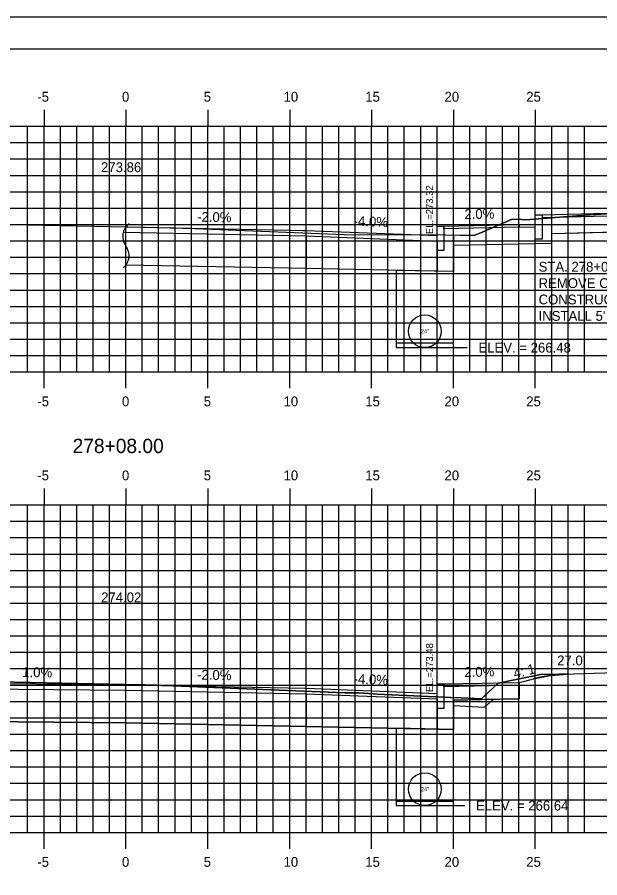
# Model space of a CAD drawing. Extents: x 854453 to 854623, y 366268 to 366378.
# Drawn here: x 854529.8 to 854565.4, y 366325.6 to 366378.2 of the extents above; entities that cross this region are included whole.
import ezdxf

# ---------------------------------------------------------------- set-up
doc = ezdxf.new("R2010")
doc.units = 0
for name, color, linetype in [('ANNOTATION', 7, 'Continuous'), ('BORDER', 7, 'Continuous'), ('D_Curb_Type1_Rt', 7, 'Continuous'), ('D_Curb_Type_1_Rt', 7, 'Continuous'), ('D_Roadway_Centerline', 7, 'Continuous'), ('D_Roadway_Centerline_Text', 7, 'Continuous'), ('D_Roadway_Edge_Shoulder', 7, 'Continuous'), ('D_Roadway_FinishedGrade', 7, 'Continuous'), ('D_Roadway_Sidewalks_Paved', 7, 'Continuous'), ('D_Roadway_SubGrade', 7, 'Continuous'), ('D_Text_Standard', 7, 'Continuous'), ('H_V ANNOTATION', 7, 'Continuous'), ('JUNK COM EXC', 7, 'Continuous'), ('junk grubnfill', 7, 'Continuous'), ('junk strct exc', 7, 'Continuous'), ('MAJOR', 7, 'Continuous'), ('MINOR', 7, 'Continuous'), ('PDRAIN', 7, 'Continuous'), ('PLOT BOUNDARY', 7, 'Continuous'), ('S_Roadway_Centerline', 7, 'Continuous')]:
    doc.layers.add(name, color=color, linetype=linetype)

msp = doc.modelspace()

# ---------------------------------------------------------------- linework, layer by layer
at = {"layer": 'BORDER'}
msp.add_line((854621.439, 366376.236), (854461.439, 366376.236), dxfattribs=at)
at = {"layer": 'D_Curb_Type1_Rt'}
msp.add_lwpolyline([(854561.855, 366366.118), (854561.855, 366364.618), (854561.439, 366364.618), (854561.439, 366366.118)], close=True, dxfattribs=at)
at = {"layer": 'D_Curb_Type_1_Rt'}
for points in [[(854555.855, 366365.423), (854555.855, 366363.923), (854555.439, 366363.923), (854555.439, 366365.423)], [(854555.855, 366337.466), (854555.855, 366335.966), (854555.439, 366335.966), (854555.439, 366337.466)]]:
    msp.add_lwpolyline(points, close=True, dxfattribs=at)
at = {"layer": 'D_Roadway_Centerline'}
msp.add_line((854547.246, 366365.163), (854547.439, 366365.159), dxfattribs=at)
at = {"layer": 'D_Roadway_Edge_Shoulder'}
for p, q in [((854536.439, 366365.379), (854547.439, 366365.159)), ((854547.439, 366365.159), (854555.437, 366364.84))]:
    msp.add_line(p, q, dxfattribs=at)
msp.add_lwpolyline([(854517.439, 366337.212), (854525.439, 366337.532), (854536.439, 366337.422), (854547.439, 366337.202), (854555.437, 366336.882)], dxfattribs=at)
at = {"layer": 'D_Roadway_FinishedGrade'}
msp.add_line((854560.444, 366337.557), (854561.318, 366337.776), dxfattribs=at)
msp.add_arc((854563.744, 366328.074), 10, 91.7748, 104.0362, dxfattribs=at)
at = {"layer": 'D_Roadway_Sidewalks_Paved'}
for p, q in [((854561.855, 366366.118), (854574.919, 366366.457)), ((854561.855, 366365.951), (854574.919, 366366.291)), ((854560.444, 366365.515), (854561.439, 366365.534)), ((854560.447, 366365.348), (854561.442, 366365.368))]:
    msp.add_line(p, q, dxfattribs=at)
for points in [[(854555.855, 366365.423), (854560.444, 366365.515), (854560.444, 366365.348), (854555.855, 366365.256)], [(854555.855, 366337.465), (854560.444, 366337.557), (854560.444, 366337.39), (854555.855, 366337.298)]]:
    msp.add_lwpolyline(points, close=True, dxfattribs=at)
at = {"layer": 'D_Roadway_SubGrade'}
for p, q in [((854536.278, 366365.049), (854547.439, 366364.826)), ((854562.439, 366364.966), (854574.919, 366365.29)), ((854562.439, 366364.387), (854562.439, 366364.966)), ((854547.439, 366364.826), (854547.439, 366362.826)), ((854556.439, 366364.267), (854562.439, 366364.387)), ((854547.439, 366362.826), (854536.439, 366363.046))]:
    msp.add_line(p, q, dxfattribs=at)
for points in [[(854547.439, 366364.826), (854555.439, 366364.506), (854555.439, 366362.666), (854547.439, 366362.826)], [(854525.439, 366335.199), (854525.439, 366337.199), (854536.439, 366337.089), (854547.439, 366336.869), (854547.439, 366334.869), (854536.439, 366335.089)], [(854547.439, 366336.869), (854555.439, 366336.549), (854555.439, 366334.709), (854547.439, 366334.869)]]:
    msp.add_lwpolyline(points, close=True, dxfattribs=at)
for points in [[(854556.439, 366364.267), (854556.439, 366362.645), (854555.439, 366362.665)], [(854560.444, 366337.39), (854560.444, 366336.557), (854556.439, 366336.477), (854556.439, 366334.688), (854555.439, 366334.708)], [(854556.439, 366336.151), (854558.328, 366336.052), (854558.863, 366336.526)]]:
    msp.add_lwpolyline(points, dxfattribs=at)
for centre, radius, start, end in [((854537.213, 366364.795), 0.969, 126.9306, 216.9306), ((854535.7, 366363.616), 0.933, 307.6674, 38.9085)]:
    msp.add_arc(centre, radius, start, end, dxfattribs=at)
at = {"layer": 'D_Text_Standard'}
for points in [[(854556.439, 366358.001), (854556.606, 366358.001), (854557.286, 366358.001)], [(854556.439, 366330.041), (854556.458, 366330.041), (854557.138, 366330.041)]]:
    msp.add_lwpolyline(points, dxfattribs=at)
at = {"layer": 'JUNK COM EXC'}
for points in [[(854556.439, 366364.877), (854556.439, 366364.267), (854556.439, 366364.267), (854562.439, 366364.387), (854562.439, 366364.966), (854574.919, 366365.29), (854574.919, 366366.457), (854571.334, 366366.391), (854568.525, 366366.364), (854564.488, 366366.083), (854560.855, 366365.814), (854560.601, 366365.825), (854560.033, 366365.848), (854558.145, 366365.029), (854557.7, 366364.856), (854556.439, 366364.877)], [(854525.439, 366335.199), (854536.439, 366335.089), (854547.439, 366334.869), (854556.439, 366334.688), (854556.439, 366336.477), (854558.151, 366336.511), (854560.444, 366336.557), (854560.444, 366337.557), (854560.881, 366337.667), (854561.318, 366337.776), (854562.368, 366337.979), (854563.434, 366338.07), (854562.879, 366338.055), (854562.453, 366338.047), (854561.76, 366338.034), (854561.162, 366337.931), (854560.167, 366337.722), (854559.173, 366337.513), (854558.15, 366336.562), (854556.914, 366336.627), (854556.266, 366336.648), (854551.776, 366336.835), (854551.532, 366336.856), (854550.966, 366336.912), (854550.652, 366336.917), (854549.806, 366336.922), (854538.309, 366337.385), (854537.601, 366337.414), (854537.42, 366337.418), (854526.661, 366337.64)]]:
    msp.add_lwpolyline(points, dxfattribs=at)
at = {"layer": 'junk grubnfill'}
msp.add_lwpolyline([(854558.863, 366336.526), (854556.439, 366336.477), (854556.439, 366336.151), (854558.328, 366336.052), (854558.863, 366336.526)], dxfattribs=at)
at = {"layer": 'junk strct exc'}
for points in [[(854552.939, 366362.716), (854552.939, 366358.301), (854556.439, 366358.301), (854556.439, 366362.645)], [(854552.939, 366334.759), (854552.939, 366330.301), (854556.439, 366330.301), (854556.439, 366334.688)]]:
    msp.add_lwpolyline(points, close=True, dxfattribs=at)
at = {"layer": 'MAJOR'}
for p, q in [((854531.439, 366372.523), (854531.439, 366371.521)), ((854536.439, 366372.523), (854536.439, 366371.521)), ((854541.439, 366372.523), (854541.439, 366371.521)), ((854546.439, 366372.523), (854546.439, 366371.521)), ((854551.439, 366372.523), (854551.439, 366371.521)), ((854556.439, 366372.523), (854556.439, 366371.521)), ((854561.439, 366372.523), (854561.439, 366371.521)), ((854466.439, 366371.521), (854606.439, 366371.521)), ((854531.439, 366356.521), (854531.439, 366371.521)), ((854536.439, 366356.521), (854536.439, 366371.521)), ((854541.439, 366356.521), (854541.439, 366371.521)), ((854546.439, 366356.521), (854546.439, 366371.521)), ((854551.439, 366356.521), (854551.439, 366371.521)), ((854556.439, 366356.521), (854556.439, 366371.521)), ((854561.439, 366356.521), (854561.439, 366371.521)), ((854466.439, 366366.521), (854606.439, 366366.521)), ((854466.439, 366361.521), (854606.439, 366361.521)), ((854466.439, 366356.521), (854606.439, 366356.521)), ((854466.439, 366356.521), (854606.439, 366356.521)), ((854531.439, 366355.519), (854531.439, 366356.521)), ((854536.439, 366355.519), (854536.439, 366356.521)), ((854541.439, 366355.519), (854541.439, 366356.521)), ((854546.439, 366355.519), (854546.439, 366356.521)), ((854551.439, 366355.519), (854551.439, 366356.521)), ((854556.439, 366355.519), (854556.439, 366356.521)), ((854561.439, 366355.519), (854561.439, 366356.521)), ((854531.439, 366349.403), (854531.439, 366348.401)), ((854536.439, 366349.403), (854536.439, 366348.401)), ((854541.439, 366349.403), (854541.439, 366348.401)), ((854546.439, 366349.403), (854546.439, 366348.401)), ((854551.439, 366349.403), (854551.439, 366348.401)), ((854556.439, 366349.403), (854556.439, 366348.401)), ((854561.439, 366349.403), (854561.439, 366348.401)), ((854466.439, 366348.401), (854606.439, 366348.401)), ((854466.439, 366348.401), (854606.439, 366348.401)), ((854531.439, 366328.401), (854531.439, 366348.401)), ((854536.439, 366328.401), (854536.439, 366348.401)), ((854541.439, 366328.401), (854541.439, 366348.401)), ((854546.439, 366328.401), (854546.439, 366348.401)), ((854551.439, 366328.401), (854551.439, 366348.401)), ((854556.439, 366328.401), (854556.439, 366348.401)), ((854561.439, 366328.401), (854561.439, 366348.401)), ((854466.439, 366343.401), (854606.439, 366343.401)), ((854466.439, 366338.401), (854606.439, 366338.401)), ((854466.439, 366333.401), (854606.439, 366333.401)), ((854466.439, 366328.401), (854606.439, 366328.401)), ((854466.439, 366328.401), (854606.439, 366328.401)), ((854531.439, 366327.399), (854531.439, 366328.401)), ((854536.439, 366327.399), (854536.439, 366328.401)), ((854541.439, 366327.399), (854541.439, 366328.401)), ((854546.439, 366327.399), (854546.439, 366328.401)), ((854551.439, 366327.399), (854551.439, 366328.401)), ((854556.439, 366327.399), (854556.439, 366328.401)), ((854561.439, 366327.399), (854561.439, 366328.401))]:
    msp.add_line(p, q, dxfattribs=at)
at = {"layer": 'MINOR'}
for p, q in [((854530.439, 366356.521), (854530.439, 366371.521)), ((854532.439, 366356.521), (854532.439, 366371.521)), ((854533.439, 366356.521), (854533.439, 366371.521)), ((854534.439, 366356.521), (854534.439, 366371.521)), ((854535.439, 366356.521), (854535.439, 366371.521)), ((854537.439, 366356.521), (854537.439, 366371.521)), ((854538.439, 366356.521), (854538.439, 366371.521)), ((854539.439, 366356.521), (854539.439, 366371.521)), ((854540.439, 366356.521), (854540.439, 366371.521)), ((854542.439, 366356.521), (854542.439, 366371.521)), ((854543.439, 366356.521), (854543.439, 366371.521)), ((854544.439, 366356.521), (854544.439, 366371.521)), ((854545.439, 366356.521), (854545.439, 366371.521)), ((854547.439, 366356.521), (854547.439, 366371.521)), ((854548.439, 366356.521), (854548.439, 366371.521)), ((854549.439, 366356.521), (854549.439, 366371.521)), ((854550.439, 366356.521), (854550.439, 366371.521)), ((854552.439, 366356.521), (854552.439, 366371.521)), ((854553.439, 366356.521), (854553.439, 366371.521)), ((854554.439, 366356.521), (854554.439, 366371.521)), ((854555.439, 366356.521), (854555.439, 366371.521)), ((854557.439, 366356.521), (854557.439, 366371.521)), ((854558.439, 366356.521), (854558.439, 366371.521)), ((854559.439, 366356.521), (854559.439, 366371.521)), ((854560.439, 366356.521), (854560.439, 366371.521)), ((854562.439, 366356.521), (854562.439, 366371.521)), ((854563.439, 366356.521), (854563.439, 366371.521)), ((854564.439, 366356.521), (854564.439, 366371.521)), ((854466.439, 366370.521), (854606.439, 366370.521)), ((854466.439, 366369.521), (854606.439, 366369.521)), ((854466.439, 366368.521), (854606.439, 366368.521)), ((854466.439, 366367.521), (854606.439, 366367.521)), ((854466.439, 366365.521), (854606.439, 366365.521)), ((854466.439, 366364.521), (854606.439, 366364.521)), ((854466.439, 366363.521), (854606.439, 366363.521)), ((854466.439, 366362.521), (854606.439, 366362.521)), ((854466.439, 366360.521), (854606.439, 366360.521)), ((854466.439, 366359.521), (854606.439, 366359.521)), ((854466.439, 366358.521), (854606.439, 366358.521)), ((854466.439, 366357.521), (854606.439, 366357.521)), ((854530.439, 366328.401), (854530.439, 366348.401)), ((854532.439, 366328.401), (854532.439, 366348.401)), ((854533.439, 366328.401), (854533.439, 366348.401)), ((854534.439, 366328.401), (854534.439, 366348.401)), ((854535.439, 366328.401), (854535.439, 366348.401)), ((854537.439, 366328.401), (854537.439, 366348.401)), ((854538.439, 366328.401), (854538.439, 366348.401)), ((854539.439, 366328.401), (854539.439, 366348.401)), ((854540.439, 366328.401), (854540.439, 366348.401)), ((854542.439, 366328.401), (854542.439, 366348.401)), ((854543.439, 366328.401), (854543.439, 366348.401)), ((854544.439, 366328.401), (854544.439, 366348.401)), ((854545.439, 366328.401), (854545.439, 366348.401)), ((854547.439, 366328.401), (854547.439, 366348.401)), ((854548.439, 366328.401), (854548.439, 366348.401)), ((854549.439, 366328.401), (854549.439, 366348.401)), ((854550.439, 366328.401), (854550.439, 366348.401)), ((854552.439, 366328.401), (854552.439, 366348.401)), ((854553.439, 366328.401), (854553.439, 366348.401)), ((854554.439, 366328.401), (854554.439, 366348.401)), ((854555.439, 366328.401), (854555.439, 366348.401)), ((854557.439, 366328.401), (854557.439, 366348.401)), ((854558.439, 366328.401), (854558.439, 366348.401)), ((854559.439, 366328.401), (854559.439, 366348.401)), ((854560.439, 366328.401), (854560.439, 366348.401)), ((854562.439, 366328.401), (854562.439, 366348.401)), ((854563.439, 366328.401), (854563.439, 366348.401)), ((854564.439, 366328.401), (854564.439, 366348.401)), ((854466.439, 366347.401), (854606.439, 366347.401)), ((854466.439, 366346.401), (854606.439, 366346.401)), ((854466.439, 366345.401), (854606.439, 366345.401)), ((854466.439, 366344.401), (854606.439, 366344.401)), ((854466.439, 366342.401), (854606.439, 366342.401)), ((854466.439, 366341.401), (854606.439, 366341.401)), ((854466.439, 366340.401), (854606.439, 366340.401)), ((854466.439, 366339.401), (854606.439, 366339.401)), ((854466.439, 366337.401), (854606.439, 366337.401)), ((854466.439, 366336.401), (854606.439, 366336.401)), ((854466.439, 366335.401), (854606.439, 366335.401)), ((854466.439, 366334.401), (854606.439, 366334.401)), ((854466.439, 366332.401), (854606.439, 366332.401)), ((854466.439, 366331.401), (854606.439, 366331.401)), ((854466.439, 366330.401), (854606.439, 366330.401)), ((854466.439, 366329.401), (854606.439, 366329.401))]:
    msp.add_line(p, q, dxfattribs=at)
at = {"layer": 'PDRAIN'}
for points in [[(854552.939, 366362.716), (854552.939, 366358.001), (854556.439, 366358.001), (854556.439, 366362.645)], [(854552.939, 366334.759), (854552.939, 366330.041), (854556.439, 366330.041), (854556.439, 366334.688)]]:
    msp.add_lwpolyline(points, dxfattribs=at)
for centre in [(854554.689, 366359.001), (854554.689, 366331.041)]:
    msp.add_circle(centre, 1, dxfattribs=at)
at = {"layer": 'PLOT BOUNDARY'}
msp.add_lwpolyline([(854453.345, 366268.177), (854623.345, 366268.177), (854623.345, 366378.177), (854453.345, 366378.177)], close=True, dxfattribs=at)
at = {"layer": 'S_Roadway_Centerline'}
for points in [[(854481.432, 366364.645), (854499.682, 366365.016), (854505.789, 366365.097), (854510.235, 366365.377), (854513.7, 366365.877), (854516.347, 366365.82), (854517.17, 366365.79), (854518.74, 366365.436), (854518.986, 366365.357), (854520.609, 366365.414), (854526.543, 366365.558), (854529.37, 366365.524), (854537.587, 366365.357), (854540.64, 366365.284), (854549.757, 366364.919), (854555.961, 366364.885), (854557.7, 366364.856), (854557.75, 366364.876), (854558.145, 366365.029), (854560.033, 366365.848), (854560.601, 366365.825), (854560.855, 366365.814), (854564.488, 366366.083), (854568.525, 366366.364)], [(854526.661, 366337.64), (854537.42, 366337.418), (854537.601, 366337.414), (854538.309, 366337.385), (854549.806, 366336.922), (854550.652, 366336.917), (854550.966, 366336.912), (854551.532, 366336.856), (854551.776, 366336.835), (854556.266, 366336.648), (854556.914, 366336.627), (854558.15, 366336.562), (854558.28, 366336.677), (854559.173, 366337.513), (854561.162, 366337.931), (854561.76, 366338.034), (854563.145, 366338.061), (854567.572, 366338.198)]]:
    msp.add_lwpolyline(points, dxfattribs=at)

# ---------------------------------------------------------------- texts
at = {"layer": 'ANNOTATION'}
for s, rotation, p in [('2.0%', 1.1484, (854557.112, 366365.848)), ('-2.0%', 358.8542, (854540.782, 366365.693)), ('-2.0%', 358.8542, (854540.782, 366365.693)), ('-4.0%', 357.7095, (854550.334, 366365.445)), ('4: 1', 14.0362, (854560.182, 366337.801)), ('1.0%', 359.4271, (854530.103, 366337.886)), ('-2.0%', 358.8542, (854540.782, 366337.735)), ('2.0%', 1.1484, (854557.112, 366337.891)), ('-4.0%', 357.7095, (854550.334, 366337.487))]:
    msp.add_text(s, height=0.6, rotation=rotation, dxfattribs=at).set_placement(p)
for s, p in [('STA. 278+08.00, RT.', (854561.639, 366362.641)), ('REMOVE CONCRETE STEPS AND SLABS.', (854561.639, 366361.641)), ("CONSTRUCT 5' PAVED WALKWAY.", (854561.639, 366360.641)), ("INSTALL 5' GRANITE CURB STEP 25' RT.", (854561.639, 366359.641))]:
    msp.add_text(s, height=0.6, dxfattribs=at).set_placement(p)
at = {"layer": 'D_Roadway_Centerline_Text'}
for s, p in [('273.86', (854534.919, 366368.719)), ('274.02', (854534.927, 366342.454))]:
    msp.add_text(s, height=0.6, dxfattribs=at).set_placement(p)
at = {"layer": 'D_Text_Standard'}
for s, p in [(' EL.=273.32', (854555.193, 366364.77)), (' EL.=273.48', (854555.193, 366336.813))]:
    msp.add_text(s, height=0.4335, rotation=90, dxfattribs=at).set_placement(p)
for s, p in [('ELEV. = 266.48', (854557.966, 366357.701)), ("27.0'", (854562.774, 366338.602)), ('ELEV. = 266.64', (854557.817, 366329.741))]:
    msp.add_text(s, height=0.6, dxfattribs=at).set_placement(p)
at = {"layer": 'H_V ANNOTATION'}
for s, height, p in [('-5', 0.6, (854531.029, 366373.021)), ('0', 0.6, (854536.198, 366373.021)), ('5', 0.6, (854541.19, 366373.021)), ('10', 0.6, (854546.064, 366373.021)), ('15', 0.6, (854551.056, 366373.021)), ('20', 0.6, (854555.893, 366373.021)), ('25', 0.6, (854560.885, 366373.021)), ('-5', 0.6, (854531.029, 366354.421)), ('0', 0.6, (854536.198, 366354.421)), ('5', 0.6, (854541.19, 366354.421)), ('10', 0.6, (854546.064, 366354.421)), ('15', 0.6, (854551.056, 366354.421)), ('20', 0.6, (854555.893, 366354.421)), ('25', 0.6, (854560.885, 366354.421)), ('278+08.00', 0.875, (854533.184, 366351.564)), ('-5', 0.6, (854531.029, 366349.901)), ('0', 0.6, (854536.198, 366349.901)), ('5', 0.6, (854541.19, 366349.901)), ('10', 0.6, (854546.064, 366349.901)), ('15', 0.6, (854551.056, 366349.901)), ('20', 0.6, (854555.893, 366349.901)), ('25', 0.6, (854560.885, 366349.901)), ('-5', 0.6, (854531.029, 366326.301)), ('0', 0.6, (854536.198, 366326.301)), ('5', 0.6, (854541.19, 366326.301)), ('10', 0.6, (854546.064, 366326.301)), ('15', 0.6, (854551.056, 366326.301)), ('20', 0.6, (854555.893, 366326.301)), ('25', 0.6, (854560.885, 366326.301))]:
    msp.add_text(s, height=height, dxfattribs=at).set_placement(p)
at = {"layer": 'PDRAIN'}
for p in [(854554.447, 366358.876), (854554.447, 366330.916)]:
    msp.add_text('24"', height=0.25, dxfattribs=at).set_placement(p)
at = {"layer": 'S_Roadway_Centerline'}
for s, p in [('C', (854537.582, 366365.357)), ('L', (854537.587, 366365.35)), ('C', (854537.595, 366337.414)), ('L', (854537.601, 366337.406))]:
    msp.add_text(s, height=0.0146, dxfattribs=at).set_placement(p)

doc.saveas('drawing.dxf')
